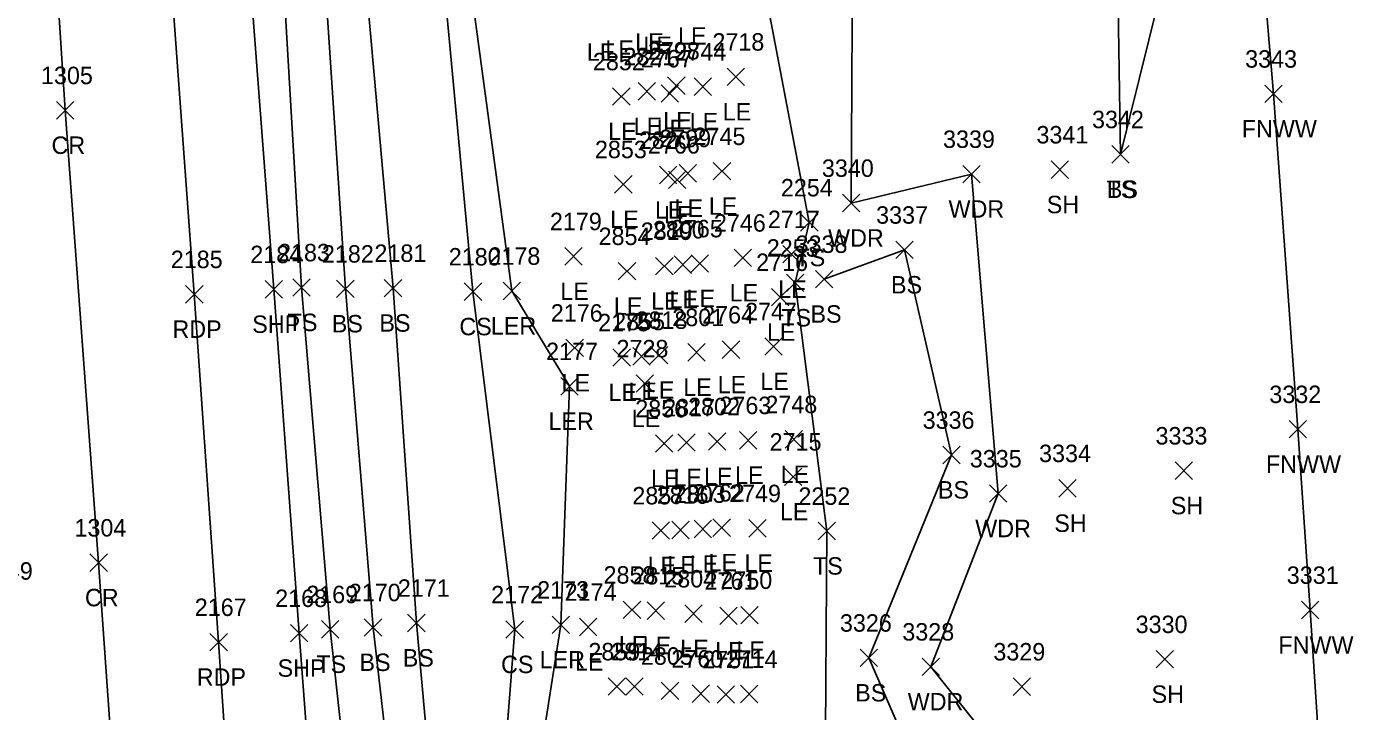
# Model space of a CAD drawing. Extents: x 1650221 to 1650634, y 244606 to 249996.
# Drawn here: x 1650353.8 to 1650505.9, y 246248.6 to 246327.1 of the extents above; entities that cross this region are included whole.
import ezdxf

# ---------------------------------------------------------------- set-up
doc = ezdxf.new("R2010")
doc.units = 0
for name, color, linetype in [('L_A', 7, 'Continuous'), ('L_I', 7, 'Continuous'), ('L_TIC', 7, 'Continuous'), ('LARO', 7, 'Continuous'), ('LAWA', 7, 'Continuous'), ('LELB', 7, 'Continuous'), ('LFNC', 7, 'Continuous'), ('LSOGP', 7, 'Continuous'), ('P_A', 7, 'Continuous'), ('P_I', 7, 'Continuous'), ('P_TIC', 7, 'Continuous'), ('PET', 7, 'Continuous'), ('PRC', 7, 'Continuous'), ('PSP', 7, 'Continuous')]:
    doc.layers.add(name, color=color, linetype=linetype)

msp = doc.modelspace()

# ---------------------------------------------------------------- linework, layer by layer
at = {"layer": 'L_TIC'}
for points in [[(1650434.1, 246320.37), (1650436.1, 246322.37)], [(1650436.1, 246320.37), (1650434.1, 246322.37)], [(1650423.89, 246318.7), (1650425.89, 246320.7)], [(1650425.89, 246318.7), (1650423.89, 246320.7)], [(1650427.27, 246319.35), (1650429.27, 246321.35)], [(1650429.27, 246319.35), (1650427.27, 246321.35)], [(1650430.31, 246319.24), (1650432.31, 246321.24)], [(1650432.31, 246319.24), (1650430.31, 246321.24)], [(1650420.97, 246318.12), (1650422.97, 246320.12)], [(1650422.97, 246318.12), (1650420.97, 246320.12)], [(1650426.52, 246318.45), (1650428.52, 246320.45)], [(1650428.52, 246318.45), (1650426.52, 246320.45)], [(1650495.75, 246318.42), (1650497.75, 246320.42)], [(1650497.75, 246318.42), (1650495.75, 246320.42)], [(1650478.19, 246311.48), (1650480.19, 246313.48)], [(1650480.19, 246311.48), (1650478.19, 246313.48)], [(1650478.19, 246311.48), (1650480.19, 246313.48)], [(1650480.19, 246311.48), (1650478.19, 246313.48)], [(1650432.51, 246309.55), (1650434.51, 246311.55)], [(1650434.51, 246309.55), (1650432.51, 246311.55)], [(1650471.25, 246309.73), (1650473.25, 246311.73)], [(1650473.25, 246309.73), (1650471.25, 246311.73)], [(1650421.2, 246308.04), (1650423.2, 246310.04)], [(1650423.2, 246308.04), (1650421.2, 246310.04)], [(1650426.33, 246309.11), (1650428.33, 246311.11)], [(1650428.33, 246309.11), (1650426.33, 246311.11)], [(1650427.37, 246308.57), (1650429.37, 246310.57)], [(1650429.37, 246308.57), (1650427.37, 246310.57)], [(1650428.58, 246309.31), (1650430.58, 246311.31)], [(1650430.58, 246309.31), (1650428.58, 246311.31)], [(1650461.12, 246309.22), (1650463.12, 246311.22)], [(1650463.12, 246309.22), (1650461.12, 246311.22)], [(1650447.31, 246305.9), (1650449.31, 246307.9)], [(1650449.31, 246305.9), (1650447.31, 246307.9)], [(1650442.52, 246303.66), (1650444.52, 246305.66)], [(1650444.52, 246303.66), (1650442.52, 246305.66)], [(1650453.44, 246300.53), (1650455.44, 246302.53)], [(1650455.44, 246300.53), (1650453.44, 246302.53)], [(1650415.48, 246299.79), (1650417.48, 246301.79)], [(1650417.48, 246299.79), (1650415.48, 246301.79)], [(1650429.96, 246298.97), (1650431.96, 246300.97)], [(1650431.96, 246298.97), (1650429.96, 246300.97)], [(1650434.89, 246299.62), (1650436.89, 246301.62)], [(1650436.89, 246299.62), (1650434.89, 246301.62)], [(1650440.47, 246300.03), (1650442.47, 246302.03)], [(1650442.47, 246300.03), (1650440.47, 246302.03)], [(1650421.62, 246298.09), (1650423.62, 246300.09)], [(1650423.62, 246298.09), (1650421.62, 246300.09)], [(1650425.9, 246298.67), (1650427.9, 246300.67)], [(1650427.9, 246298.67), (1650425.9, 246300.67)], [(1650428.01, 246298.84), (1650430.01, 246300.84)], [(1650430.01, 246298.84), (1650428.01, 246300.84)], [(1650384.3, 246296.22), (1650386.3, 246298.22)], [(1650386.3, 246296.22), (1650384.3, 246298.22)], [(1650389.33, 246296.07), (1650391.33, 246298.07)], [(1650391.33, 246296.07), (1650389.33, 246298.07)], [(1650394.79, 246296.15), (1650396.79, 246298.15)], [(1650396.79, 246296.15), (1650394.79, 246298.15)], [(1650440.9, 246296.75), (1650442.9, 246298.75)], [(1650442.9, 246296.75), (1650440.9, 246298.75)], [(1650444.21, 246297.18), (1650446.21, 246299.18)], [(1650446.21, 246297.18), (1650444.21, 246299.18)], [(1650403.96, 246295.74), (1650405.96, 246297.74)], [(1650405.96, 246295.74), (1650403.96, 246297.74)], [(1650408.42, 246295.82), (1650410.42, 246297.82)], [(1650410.42, 246295.82), (1650408.42, 246297.82)], [(1650439.17, 246295.11), (1650441.17, 246297.11)], [(1650441.17, 246295.11), (1650439.17, 246297.11)], [(1650415.62, 246289.3), (1650417.62, 246291.3)], [(1650417.62, 246289.3), (1650415.62, 246291.3)], [(1650423.29, 246288.32), (1650425.29, 246290.32)], [(1650425.29, 246288.32), (1650423.29, 246290.32)], [(1650425.29, 246288.47), (1650427.29, 246290.47)], [(1650427.29, 246288.47), (1650425.29, 246290.47)], [(1650429.59, 246288.79), (1650431.59, 246290.79)], [(1650431.59, 246288.79), (1650429.59, 246290.79)], [(1650433.54, 246289.09), (1650435.54, 246291.09)], [(1650435.54, 246289.09), (1650433.54, 246291.09)], [(1650438.41, 246289.46), (1650440.41, 246291.46)], [(1650440.41, 246289.46), (1650438.41, 246291.46)], [(1650421, 246288.2), (1650423, 246290.2)], [(1650423, 246288.2), (1650421, 246290.2)], [(1650423.67, 246285.21), (1650425.67, 246287.21)], [(1650425.67, 246285.21), (1650423.67, 246287.21)], [(1650415.03, 246284.89), (1650417.03, 246286.89)], [(1650417.03, 246284.89), (1650415.03, 246286.89)], [(1650498.52, 246279.97), (1650500.52, 246281.97)], [(1650500.52, 246279.97), (1650498.52, 246281.97)], [(1650425.88, 246278.33), (1650427.88, 246280.33)], [(1650427.88, 246278.33), (1650425.88, 246280.33)], [(1650428.45, 246278.44), (1650430.45, 246280.44)], [(1650430.45, 246278.44), (1650428.45, 246280.44)], [(1650431.96, 246278.57), (1650433.96, 246280.57)], [(1650433.96, 246278.57), (1650431.96, 246280.57)], [(1650435.52, 246278.7), (1650437.52, 246280.7)], [(1650437.52, 246278.7), (1650435.52, 246280.7)], [(1650440.74, 246278.81), (1650442.74, 246280.81)], [(1650442.74, 246278.81), (1650440.74, 246280.81)], [(1650458.82, 246277.02), (1650460.82, 246279.02)], [(1650460.82, 246277.02), (1650458.82, 246279.02)], [(1650485.47, 246275.22), (1650487.47, 246277.22)], [(1650487.47, 246275.22), (1650485.47, 246277.22)], [(1650440.66, 246274.52), (1650442.66, 246276.52)], [(1650442.66, 246274.52), (1650440.66, 246276.52)], [(1650472.12, 246273.2), (1650474.12, 246275.2)], [(1650474.12, 246273.2), (1650472.12, 246275.2)], [(1650464.18, 246272.59), (1650466.18, 246274.59)], [(1650466.18, 246272.59), (1650464.18, 246274.59)], [(1650430.32, 246268.53), (1650432.32, 246270.53)], [(1650432.32, 246268.53), (1650430.32, 246270.53)], [(1650432.47, 246268.68), (1650434.47, 246270.68)], [(1650434.47, 246268.68), (1650432.47, 246270.68)], [(1650436.59, 246268.61), (1650438.59, 246270.61)], [(1650438.59, 246268.61), (1650436.59, 246270.61)], [(1650425.49, 246268.35), (1650427.49, 246270.35)], [(1650427.49, 246268.35), (1650425.49, 246270.35)], [(1650427.76, 246268.42), (1650429.76, 246270.42)], [(1650429.76, 246268.42), (1650427.76, 246270.42)], [(1650444.53, 246268.3), (1650446.53, 246270.3)], [(1650446.53, 246268.3), (1650444.53, 246270.3)], [(1650422.19, 246259.27), (1650424.19, 246261.27)], [(1650424.19, 246259.27), (1650422.19, 246261.27)], [(1650424.93, 246259.17), (1650426.93, 246261.17)], [(1650426.93, 246259.17), (1650424.93, 246261.17)], [(1650429.23, 246258.83), (1650431.23, 246260.83)], [(1650431.23, 246258.83), (1650429.23, 246260.83)], [(1650433.25, 246258.57), (1650435.25, 246260.57)], [(1650435.25, 246258.57), (1650433.25, 246260.57)], [(1650435.67, 246258.66), (1650437.67, 246260.66)], [(1650437.67, 246258.66), (1650435.67, 246260.66)], [(1650499.95, 246259.24), (1650501.95, 246261.24)], [(1650501.95, 246259.24), (1650499.95, 246261.24)], [(1650387.59, 246257.03), (1650389.59, 246259.03)], [(1650389.59, 246257.03), (1650387.59, 246259.03)], [(1650392.5, 246257.25), (1650394.5, 246259.25)], [(1650394.5, 246257.25), (1650392.5, 246259.25)], [(1650397.47, 246257.76), (1650399.47, 246259.76)], [(1650399.47, 246257.76), (1650397.47, 246259.76)], [(1650408.74, 246257.01), (1650410.74, 246259.01)], [(1650410.74, 246257.01), (1650408.74, 246259.01)], [(1650414.02, 246257.55), (1650416.02, 246259.55)], [(1650416.02, 246257.55), (1650414.02, 246259.55)], [(1650417.17, 246257.3), (1650419.17, 246259.3)], [(1650419.17, 246257.3), (1650417.17, 246259.3)], [(1650449.34, 246253.76), (1650451.34, 246255.76)], [(1650451.34, 246253.76), (1650449.34, 246255.76)], [(1650483.28, 246253.6), (1650485.28, 246255.6)], [(1650485.28, 246253.6), (1650483.28, 246255.6)], [(1650456.44, 246252.74), (1650458.44, 246254.74)], [(1650458.44, 246252.74), (1650456.44, 246254.74)], [(1650420.46, 246250.47), (1650422.46, 246252.47)], [(1650422.46, 246250.47), (1650420.46, 246252.47)], [(1650422.49, 246250.48), (1650424.49, 246252.48)], [(1650424.49, 246250.48), (1650422.49, 246252.48)], [(1650466.89, 246250.46), (1650468.89, 246252.46)], [(1650468.89, 246250.46), (1650466.89, 246252.46)], [(1650426.55, 246249.97), (1650428.55, 246251.97)], [(1650428.55, 246249.97), (1650426.55, 246251.97)], [(1650430.09, 246249.65), (1650432.09, 246251.65)], [(1650432.09, 246249.65), (1650430.09, 246251.65)], [(1650432.94, 246249.56), (1650434.94, 246251.56)], [(1650434.94, 246249.56), (1650432.94, 246251.56)], [(1650435.62, 246249.61), (1650437.62, 246251.61)], [(1650437.62, 246249.61), (1650435.62, 246251.61)]]:
    msp.add_lwpolyline(points, dxfattribs=at)
at = {"layer": 'LARO'}
msp.add_lwpolyline([(1650408.62, 246217.57), (1650415.02, 246258.55), (1650416.03, 246285.89), (1650409.42, 246296.82), (1650403.38, 246341.57), (1650407.27, 246374.55), (1650399.81, 246378.86), (1650397.58, 246413.38), (1650396.61, 246418.12), (1650404.55, 246441.77), (1650400.93, 246459.09), (1650402.01, 246482.67), (1650393.67, 246489.39), (1650391.87, 246506.08), (1650398.3, 246543.79), (1650391.28, 246548.76), (1650385.03, 246598.74), (1650385.05, 246648.92)], dxfattribs=at)
at = {"layer": 'LAWA'}
msp.add_lwpolyline([(1650467.45, 246241.25), (1650457.44, 246253.74), (1650465.18, 246273.59), (1650462.12, 246310.22), (1650448.31, 246306.9), (1650448.47, 246334.54), (1650451.18, 246360.81), (1650449.4, 246391.83), (1650443.67, 246414.29), (1650436.75, 246442.34), (1650433.96, 246470.02), (1650430.34, 246504.78), (1650427.12, 246530.84), (1650425.66, 246560.12), (1650421.39, 246581.34), (1650411.43, 246590.25), (1650407.77, 246596.47), (1650408.99, 246611.27), (1650406.47, 246635.27)], dxfattribs=at)
at = {"layer": 'LELB'}
for points in [[(1650393.27, 246215.06), (1650388.59, 246258.03), (1650385.3, 246297.22), (1650382.89, 246338.27), (1650379.78, 246382.54), (1650376.7, 246415.11), (1650373.39, 246460.52), (1650370.35, 246509.11), (1650367.73, 246551.79), (1650362.79, 246601.35), (1650360.91, 246643.93), (1650360.73, 246683.45), (1650355.99, 246728.59), (1650353.01, 246770.02), (1650352.21, 246793.58), (1650347.7, 246827.18)], [(1650406.66, 246218.25), (1650409.74, 246258.01), (1650404.96, 246296.74), (1650400.85, 246340.5), (1650395.59, 246379.71), (1650393.17, 246415.1), (1650394.55, 246457.78), (1650389.36, 246506.84), (1650386.12, 246550.61), (1650380.92, 246598.97), (1650378.98, 246645.95), (1650376.23, 246684.96), (1650377.19, 246729.69), (1650373.96, 246768.95), (1650374.9, 246794.97)], [(1650398.42, 246215.35), (1650393.5, 246258.25), (1650390.33, 246297.07), (1650387.57, 246339.17), (1650383.09, 246382.59), (1650381.54, 246415.75), (1650379.32, 246460.8), (1650374.72, 246508.95), (1650372.6, 246551.63), (1650368.85, 246601.31), (1650366.31, 246644.43), (1650364.47, 246684.58), (1650363.63, 246728.26), (1650358.66, 246769.4), (1650355.43, 246788.13), (1650360.4, 246788.44)], [(1650402.25, 246216.69), (1650398.47, 246258.76), (1650395.79, 246297.15), (1650391.97, 246340.1), (1650387.54, 246382.07), (1650385.71, 246415.98), (1650383.05, 246460.21), (1650379.09, 246508.87), (1650375.79, 246552.14), (1650373.14, 246601), (1650370.95, 246644.96), (1650368.35, 246684.96), (1650368, 246727.84), (1650362.74, 246769.21), (1650360.4, 246788.44)], [(1650479.19, 246312.48), (1650486.78, 246343.04), (1650484.86, 246368.89), (1650480.94, 246392.32), (1650477.18, 246421.11), (1650468.88, 246443.02), (1650461.43, 246474.29), (1650459.99, 246504.26), (1650455.48, 246533.7), (1650468.39, 246557.95), (1650462.64, 246596.83), (1650458.65, 246616.06), (1650445.95, 246610.52), (1650432.73, 246599.27), (1650420.88, 246596.79), (1650423.87, 246613.47), (1650428.27, 246642.15), (1650440.67, 246654.81), (1650470.88, 246672.08), (1650450.6, 246689.53), (1650437.54, 246708.06), (1650451.69, 246713.27), (1650467.72, 246712.4)], [(1650445.18, 246217.4), (1650445.53, 246269.3), (1650441.9, 246297.75), (1650443.52, 246304.66), (1650437.79, 246334.62), (1650435.28, 246374.91), (1650430.35, 246417), (1650432.13, 246431.96), (1650424.25, 246446.43), (1650422.05, 246472.52), (1650416.53, 246502.71), (1650417.53, 246540.78), (1650409.48, 246565.5), (1650407.87, 246589.87), (1650402.92, 246599.27), (1650397.78, 246634.8)], [(1650479.19, 246312.48), (1650478.72, 246341.58), (1650480.51, 246366.06), (1650476.32, 246392.29), (1650469.92, 246418.18), (1650461.39, 246442.98), (1650452.29, 246471.6), (1650451.91, 246505.83), (1650450.21, 246533.17), (1650459.89, 246559.37), (1650456.99, 246596.58), (1650458.65, 246616.06)], [(1650463.49, 246169.04), (1650459.01, 246190.47), (1650451.22, 246213.22), (1650448.61, 246231.19), (1650455.93, 246241.94), (1650450.34, 246254.76), (1650459.82, 246278.02), (1650454.44, 246301.53), (1650445.21, 246298.18)]]:
    msp.add_lwpolyline(points, dxfattribs=at)
at = {"layer": 'LFNC'}
msp.add_lwpolyline([(1650503.06, 246228.04), (1650500.95, 246260.24), (1650499.52, 246280.97), (1650496.75, 246319.42), (1650494.71, 246343.47), (1650493.4, 246369.97), (1650491.44, 246391.35), (1650489.38, 246422.28), (1650487.8, 246445.43), (1650485.64, 246474.81), (1650483.6, 246501.15), (1650481.03, 246533.54), (1650479.37, 246558.3), (1650476.37, 246602.1), (1650473.83, 246635.82)], dxfattribs=at)
at = {"layer": 'LSOGP'}
msp.add_lwpolyline([(1650503.06, 246228.04), (1650500.95, 246260.24), (1650499.52, 246280.97), (1650496.75, 246319.42), (1650494.71, 246343.47), (1650493.4, 246369.97), (1650491.44, 246391.35), (1650489.38, 246422.28), (1650487.8, 246445.43), (1650485.64, 246474.81), (1650483.6, 246501.15), (1650481.03, 246533.54), (1650479.37, 246558.3), (1650476.37, 246602.1), (1650473.83, 246635.82)], dxfattribs=at)
at = {"layer": 'P_TIC'}
for points in [[(1650357.21, 246316.53), (1650359.21, 246318.53)], [(1650359.21, 246316.53), (1650357.21, 246318.53)], [(1650381.12, 246296.01), (1650383.12, 246298.01)], [(1650383.12, 246296.01), (1650381.12, 246298.01)], [(1650372.01, 246295.44), (1650374.01, 246297.44)], [(1650374.01, 246295.44), (1650372.01, 246297.44)], [(1650361.04, 246264.67), (1650363.04, 246266.67)], [(1650363.04, 246264.67), (1650361.04, 246266.67)], [(1650384.02, 246256.59), (1650386.02, 246258.59)], [(1650386.02, 246256.59), (1650384.02, 246258.59)], [(1650374.8, 246255.56), (1650376.8, 246257.56)], [(1650376.8, 246255.56), (1650374.8, 246257.56)]]:
    msp.add_lwpolyline(points, dxfattribs=at)
at = {"layer": 'PET'}
msp.add_lwpolyline([(1650378.63, 246214.91), (1650375.8, 246256.56), (1650373.01, 246296.44), (1650370.08, 246336.2), (1650366.98, 246382.9), (1650364.95, 246414.8), (1650361.94, 246459.78), (1650357.93, 246508.74), (1650354.58, 246551.74), (1650350.86, 246600.91), (1650347.48, 246643.7), (1650346.09, 246667.41)], dxfattribs=at)
at = {"layer": 'PRC'}
msp.add_lwpolyline([(1650365.1, 246222.23), (1650362.04, 246265.67), (1650358.21, 246317.53), (1650354.88, 246368.98), (1650350.4, 246428.86), (1650346.57, 246483.13), (1650341.97, 246537.02), (1650338.57, 246591.04), (1650334.55, 246647.32), (1650330.72, 246698.07), (1650326.82, 246753.45), (1650322.93, 246808.73), (1650318.78, 246866.3), (1650315.63, 246915.25), (1650311.69, 246971.18), (1650308.09, 247021.19), (1650305.21, 247068.94), (1650301.6, 247120.36), (1650298.8, 247160.8), (1650294.82, 247207.2), (1650291.45, 247257.79)], dxfattribs=at)
at = {"layer": 'PSP'}
msp.add_lwpolyline([(1650388.25, 246215.07), (1650385.02, 246257.59), (1650382.12, 246297.01), (1650379.04, 246337.67), (1650376.28, 246382.91), (1650373.45, 246415.13), (1650370.45, 246460.18), (1650366.83, 246508.93), (1650363.56, 246551.91), (1650360.5, 246601.39), (1650356.68, 246643.63), (1650355.13, 246668.21)], dxfattribs=at)

# ---------------------------------------------------------------- texts
at = {"layer": 'L_A'}
for s, p in [('LE', (1650428.47, 246325.06)), ('LE', (1650420.14, 246323.54)), ('LE', (1650423.55, 246324.37)), ('LE', (1650424.49, 246323.99)), ('LE', (1650418.01, 246323.21)), ('LE', (1650433.59, 246316.37)), ('LE', (1650420.46, 246314.12)), ('LE', (1650423.38, 246314.7)), ('LE', (1650426.01, 246314.45)), ('LE', (1650426.76, 246315.35)), ('LE', (1650429.8, 246315.24)), ('FNWW', (1650493.1, 246314.42)), ('TS', (1650477.6, 246307.48)), ('BS', (1650477.63, 246307.48)), ('LE', (1650425.82, 246305.11)), ('LE', (1650428.07, 246305.31)), ('LE', (1650431.99, 246305.55)), ('WDR', (1650459.48, 246305.22)), ('SH', (1650470.74, 246305.73)), ('LE', (1650420.69, 246304.04)), ('LE', (1650426.86, 246304.57)), ('WDR', (1650445.67, 246301.9)), ('TS', (1650441.93, 246299.66)), ('LE', (1650439.95, 246296.03)), ('BS', (1650452.88, 246296.53)), ('LE', (1650414.97, 246295.79)), ('LE', (1650425.38, 246294.67)), ('LE', (1650427.5, 246294.84)), ('LE', (1650429.44, 246294.97)), ('LE', (1650434.38, 246295.62)), ('LE', (1650421.11, 246294.09)), ('BS', (1650443.65, 246293.18)), ('TS', (1650383.71, 246292.22)), ('BS', (1650388.77, 246292.07)), ('BS', (1650394.23, 246292.15)), ('CS', (1650403.4, 246291.74)), ('LER', (1650407.01, 246291.82)), ('TS', (1650440.31, 246292.75)), ('LE', (1650438.66, 246291.11)), ('LE', (1650415.11, 246285.3)), ('LE', (1650437.9, 246285.46)), ('LE', (1650420.49, 246284.2)), ('LE', (1650422.78, 246284.32)), ('LE', (1650424.78, 246284.47)), ('LE', (1650429.07, 246284.79)), ('LE', (1650433.02, 246285.09)), ('LER', (1650413.61, 246280.89)), ('LE', (1650423.15, 246281.21)), ('LE', (1650431.45, 246274.57)), ('LE', (1650435, 246274.7)), ('LE', (1650440.23, 246274.81)), ('FNWW', (1650495.87, 246275.97)), ('LE', (1650425.37, 246274.33)), ('LE', (1650427.94, 246274.44)), ('BS', (1650458.26, 246273.02)), ('LE', (1650440.15, 246270.52)), ('SH', (1650484.96, 246271.22)), ('WDR', (1650462.54, 246268.59)), ('SH', (1650471.61, 246269.2)), ('LE', (1650424.98, 246264.35)), ('LE', (1650427.25, 246264.42)), ('LE', (1650429.81, 246264.53)), ('LE', (1650431.96, 246264.68)), ('LE', (1650436.08, 246264.61)), ('TS', (1650443.94, 246264.3)), ('LE', (1650421.68, 246255.27)), ('LE', (1650424.41, 246255.17)), ('LE', (1650428.72, 246254.83)), ('FNWW', (1650497.3, 246255.24)), ('BS', (1650391.94, 246253.25)), ('BS', (1650396.91, 246253.76)), ('LER', (1650412.6, 246253.55)), ('LE', (1650416.65, 246253.3)), ('LE', (1650432.73, 246254.57)), ('LE', (1650435.16, 246254.66)), ('TS', (1650387, 246253.03)), ('CS', (1650408.18, 246253.01)), ('BS', (1650448.78, 246249.76)), ('WDR', (1650454.8, 246248.74)), ('SH', (1650482.76, 246249.6))]:
    msp.add_text(s, height=2, dxfattribs=at).set_placement(p)
at = {"layer": 'L_I'}
for s, p in [('2798', (1650425.01, 246323.35)), ('2744', (1650428.05, 246323.24)), ('2718', (1650432.41, 246324.37)), ('2852', (1650418.71, 246322.12)), ('2821', (1650422.2, 246322.7)), ('2767', (1650424.21, 246322.45)), ('3343', (1650493.49, 246322.42)), ('3342', (1650475.93, 246315.48)), ('3342', (1650475.93, 246315.48)), ('2820', (1650423.98, 246313.11)), ('2766', (1650425.01, 246312.57)), ('2799', (1650426.31, 246313.31)), ('2745', (1650430.25, 246313.55)), ('3339', (1650458.85, 246313.22)), ('3341', (1650469.56, 246313.73)), ('2853', (1650418.94, 246312.04)), ('3340', (1650444.96, 246309.9)), ('2254', (1650440.26, 246307.66)), ('2179', (1650413.78, 246303.79)), ('2746', (1650432.58, 246303.62)), ('2717', (1650438.77, 246304.03)), ('3337', (1650451.18, 246304.53)), ('2854', (1650419.36, 246302.09)), ('2819', (1650424.19, 246302.67)), ('2800', (1650425.58, 246302.84)), ('2765', (1650427.65, 246302.97)), ('2253', (1650438.64, 246300.75)), ('3338', (1650441.95, 246301.18)), ('2183', (1650382.61, 246300.22)), ('2182', (1650387.64, 246300.07)), ('2181', (1650393.66, 246300.15)), ('2180', (1650402.18, 246299.74)), ('2178', (1650406.73, 246299.82)), ('2716', (1650437.42, 246299.11)), ('2176', (1650413.88, 246293.3)), ('2801', (1650427.81, 246292.79)), ('2764', (1650431.23, 246293.09)), ('2747', (1650436.15, 246293.46)), ('2175', (1650419.31, 246292.2)), ('2855', (1650421.03, 246292.32)), ('2818', (1650423.6, 246292.47)), ('2177', (1650413.34, 246288.89)), ('2728', (1650421.41, 246289.21)), ('3332', (1650496.26, 246283.97)), ('2856', (1650423.57, 246282.33)), ('2817', (1650426.76, 246282.44)), ('2802', (1650429.62, 246282.57)), ('2763', (1650433.21, 246282.7)), ('2748', (1650438.48, 246282.81)), ('3336', (1650456.51, 246281.02)), ('3333', (1650483.21, 246279.22)), ('2715', (1650438.97, 246278.52)), ('3335', (1650461.92, 246276.59)), ('3334', (1650469.86, 246277.2)), ('2857', (1650423.23, 246272.35)), ('2816', (1650426.02, 246272.42)), ('2803', (1650427.98, 246272.53)), ('2762', (1650430.16, 246272.68)), ('2749', (1650434.32, 246272.61)), ('2252', (1650442.27, 246272.3)), ('2858', (1650419.93, 246263.27)), ('2815', (1650423.23, 246263.17)), ('2804', (1650426.89, 246262.83)), ('2761', (1650431.51, 246262.57)), ('2750', (1650433.32, 246262.66)), ('3331', (1650498.26, 246263.24)), ('2169', (1650385.84, 246261.03)), ('2170', (1650390.72, 246261.25)), ('2171', (1650396.34, 246261.76)), ('2172', (1650407.04, 246261.01)), ('2173', (1650412.32, 246261.55)), ('2174', (1650415.47, 246261.3)), ('3326', (1650447.03, 246257.76)), ('3328', (1650454.18, 246256.74)), ('3330', (1650480.93, 246257.6)), ('2859', (1650418.19, 246254.47)), ('2814', (1650420.8, 246254.48)), ('2805', (1650424.21, 246253.97)), ('2760', (1650427.7, 246253.65)), ('2751', (1650431.25, 246253.56)), ('2714', (1650433.93, 246253.61)), ('3329', (1650464.62, 246254.46))]:
    msp.add_text(s, height=2, dxfattribs=at).set_placement(p)
at = {"layer": 'P_A'}
for s, p in [('CR', (1650356.64, 246312.53)), ('RDP', (1650370.5, 246291.44)), ('SHP', (1650379.65, 246292.01)), ('CR', (1650360.47, 246260.67)), ('SHP', (1650382.56, 246252.59)), ('RDP', (1650373.29, 246251.56))]:
    msp.add_text(s, height=2, dxfattribs=at).set_placement(p)
at = {"layer": 'P_I'}
for s, p in [('1305', (1650355.43, 246320.53)), ('2185', (1650370.31, 246299.44)), ('2184', (1650379.43, 246300.01)), ('1304', (1650359.27, 246268.67)), ('1149', (1650348.54, 246263.72)), ('2167', (1650373.06, 246259.56)), ('2168', (1650382.28, 246260.59))]:
    msp.add_text(s, height=2, dxfattribs=at).set_placement(p)

doc.saveas('drawing.dxf')
